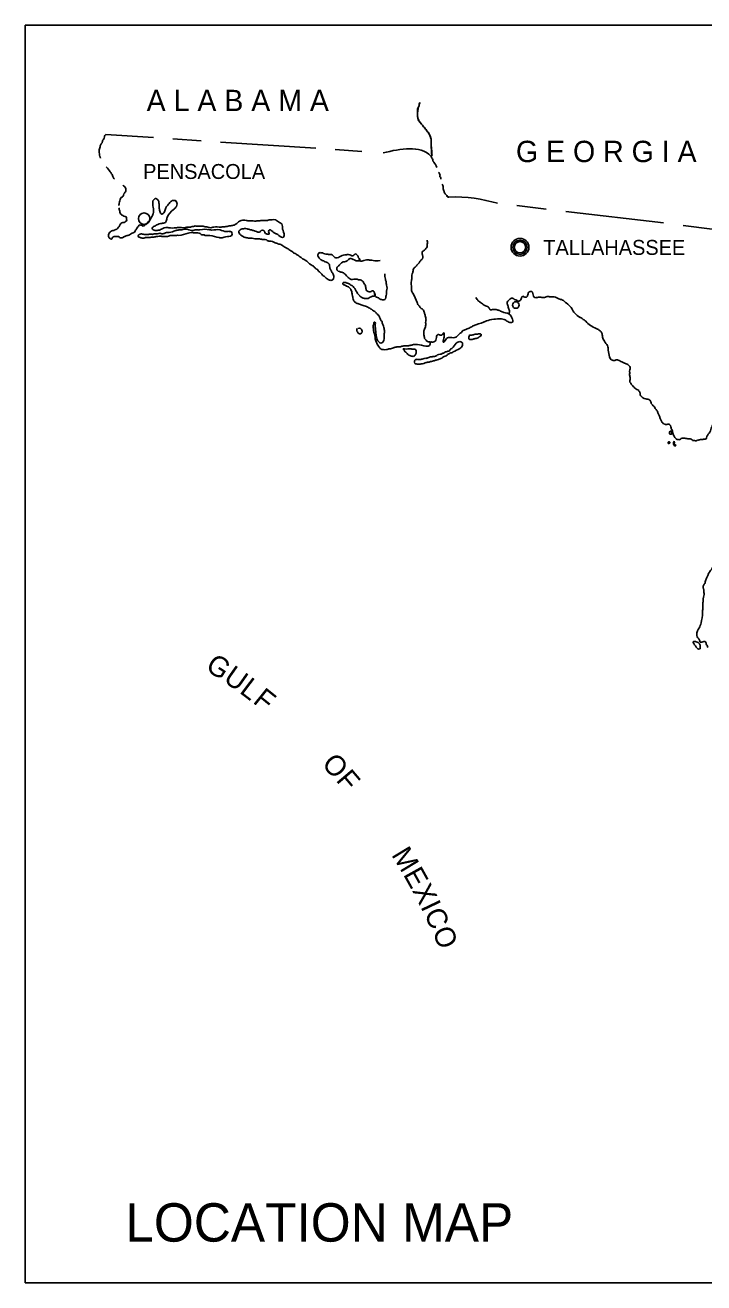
# Model space of a CAD drawing. Extents: x 565003 to 644146, y 1916234 to 1975957.
# Drawn here: x 620713 to 628733, y 1961029 to 1975886 of the extents above; entities that cross this region are included whole.
import ezdxf

# ---------------------------------------------------------------- set-up
doc = ezdxf.new("R2010")
doc.units = 0
doc.layers.add('C-TAXI-CNTR', color=7, linetype='Continuous')

msp = doc.modelspace()

# ---------------------------------------------------------------- linework, layer by layer
at = {"layer": 'C-TAXI-CNTR'}
for p, q in [((637179, 1975886), (620713, 1975886)), ((620713, 1975886), (620713, 1961029)), ((622229, 1974557), (621667, 1974595)), ((622794, 1974519), (622460, 1974542)), ((624149, 1974431), (623023, 1974505)), ((624692, 1974393), (624378, 1974415)), ((626871, 1973713), (626525, 1973754)), ((628256, 1973549), (627103, 1973685)), ((628833, 1973477), (628490, 1973520)), ((626465, 1972428), (626464, 1972430)), ((620713, 1961029), (637179, 1961029))]:
    msp.add_line(p, q, dxfattribs=at)
for centre, radius in [((622119, 1973600), 67.1), ((626561, 1973262), 105), ((626561, 1973262), 83.9), ((626561, 1973262), 67.1), ((626513, 1972580), 39)]:
    msp.add_circle(centre, radius, dxfattribs=at)
msp.add_arc((625737, 1973901), 50.8, 213.1829, 248.6294, dxfattribs=at)
for points in [[(625521, 1974345), (625517, 1974368), (625517, 1974408), (625513, 1974453), (625513, 1974506), (625505, 1974558), (625490, 1974595), (625469, 1974627), (625438, 1974668), (625397, 1974717), (625365, 1974757), (625350, 1974808), (625351, 1974869), (625356, 1974915), (625370, 1974938), (625370, 1974951), (625381, 1974974)], [(625522, 1974344), (625519, 1974353), (625519, 1974393), (625513, 1974435), (625513, 1974513), (625507, 1974551), (625493, 1974590), (625469, 1974629), (625460, 1974638), (625442, 1974665), (625421, 1974686), (625394, 1974722), (625375, 1974743), (625357, 1974780), (625351, 1974813), (625351, 1974858), (625354, 1974885), (625357, 1974896), (625360, 1974923), (625369, 1974938), (625372, 1974956), (625381, 1974974)], [(621667, 1974595), (621656, 1974584), (621650, 1974565), (621643, 1974541), (621629, 1974522), (621624, 1974503), (621618, 1974491), (621611, 1974484), (621598, 1974450), (621592, 1974425), (621588, 1974399), (621591, 1974366), (621596, 1974334), (621600, 1974323), (621604, 1974314)], [(625577, 1974206), (625542, 1974269), (625536, 1974277), (625531, 1974284), (625529, 1974296), (625520, 1974314), (625510, 1974339), (625509, 1974340), (624943, 1974378)], [(621669, 1974214), (621688, 1974195), (621701, 1974176), (621719, 1974153), (621740, 1974120), (621749, 1974098), (621768, 1974065)], [(625627, 1974067), (625625, 1974082), (625615, 1974096), (625616, 1974111), (625598, 1974149)], [(621866, 1973995), (621882, 1973983), (621898, 1973965), (621905, 1973942), (621899, 1973917), (621886, 1973903), (621863, 1973858), (621849, 1973849), (621837, 1973827), (621830, 1973797), (621823, 1973772), (621822, 1973755)], [(626295, 1973785), (625720, 1973853), (625707, 1973854), (625695, 1973873), (625676, 1973894), (625667, 1973906), (625664, 1973919), (625655, 1973939), (625654, 1973966), (625650, 1973991), (625643, 1974006)], [(621821, 1973729), (621825, 1973708), (621831, 1973690), (621834, 1973675), (621843, 1973654), (621852, 1973645), (621867, 1973636), (621894, 1973627), (621909, 1973618), (621912, 1973597), (621912, 1973574), (621900, 1973565), (621885, 1973556), (621867, 1973556), (621830, 1973517), (621818, 1973498), (621797, 1973477), (621773, 1973468), (621764, 1973462), (621749, 1973459), (621713, 1973439), (621701, 1973421), (621698, 1973400), (621698, 1973388), (621719, 1973364), (621734, 1973358), (621752, 1973385), (621782, 1973391), (621794, 1973391), (621815, 1973388), (621830, 1973379), (621854, 1973372), (621869, 1973378), (621881, 1973387), (621893, 1973390), (621908, 1973396), (621947, 1973408), (621971, 1973424), (622004, 1973442), (622019, 1973463), (622028, 1973481), (622043, 1973502), (622061, 1973522), (622082, 1973525), (622097, 1973519), (622106, 1973513), (622124, 1973519), (622133, 1973528), (622142, 1973531), (622160, 1973549), (622208, 1973619), (622226, 1973658), (622226, 1973735), (622221, 1973795), (622224, 1973811), (622236, 1973826), (622242, 1973832), (622257, 1973838), (622275, 1973829), (622295, 1973793), (622295, 1973784), (622298, 1973766), (622298, 1973729), (622304, 1973690), (622328, 1973654), (622337, 1973657), (622352, 1973669), (622373, 1973718), (622391, 1973751), (622400, 1973760), (622433, 1973801), (622451, 1973813), (622472, 1973816), (622490, 1973813), (622505, 1973789), (622508, 1973777), (622502, 1973745), (622467, 1973709), (622392, 1973615), (622380, 1973570), (622371, 1973556), (622347, 1973547), (622329, 1973544), (622269, 1973526), (622254, 1973517), (622215, 1973489), (622218, 1973474), (622236, 1973465), (622260, 1973459), (622272, 1973462), (622302, 1973465)], [(622302, 1973465), (622314, 1973472), (622332, 1973478), (622341, 1973484), (622356, 1973490), (622392, 1973496), (622410, 1973493), (622493, 1973492), (622514, 1973495), (622604, 1973495), (622643, 1973501), (622667, 1973501), (622685, 1973508), (622703, 1973508), (622724, 1973514), (622742, 1973511), (622818, 1973511), (622839, 1973505), (622860, 1973502), (622881, 1973496), (622932, 1973498), (622941, 1973501), (623028, 1973501), (623058, 1973504), (623073, 1973504), (623126, 1973514), (623147, 1973517), (623156, 1973520), (623165, 1973520), (623204, 1973535), (623213, 1973541), (623225, 1973555), (623246, 1973570), (623267, 1973579), (623324, 1973579), (623363, 1973573), (623384, 1973573), (623396, 1973574), (623423, 1973571), (623438, 1973571), (623462, 1973574), (623477, 1973574), (623516, 1973580), (623577, 1973580), (623595, 1973585), (623610, 1973585), (623631, 1973588), (623667, 1973588), (623685, 1973579), (623709, 1973561), (623745, 1973537), (623756, 1973477), (623774, 1973403), (623765, 1973382), (623741, 1973382), (623684, 1973421), (623672, 1973424), (623645, 1973442), (623639, 1973448), (623622, 1973460), (623601, 1973469), (623592, 1973460), (623592, 1973438), (623597, 1973420), (623585, 1973417), (623565, 1973420), (623547, 1973435), (623544, 1973444), (623532, 1973462), (623502, 1973459), (623490, 1973444), (623433, 1973453), (623412, 1973459), (623397, 1973465), (623355, 1973474), (623336, 1973480), (623276, 1973478), (623240, 1973454), (623262, 1973406), (623289, 1973388), (623301, 1973382), (623322, 1973376), (623361, 1973370), (623382, 1973370), (623442, 1973361), (623472, 1973361), (623516, 1973355), (623537, 1973354), (623564, 1973348), (623582, 1973339), (623591, 1973336)], [(622062, 1973414), (622061, 1973412), (622053, 1973408), (622050, 1973400), (622050, 1973390), (622053, 1973382), (622064, 1973381), (622080, 1973375), (622088, 1973373), (622095, 1973370), (622115, 1973370), (622122, 1973373), (622137, 1973376)], [(622062, 1973414), (622070, 1973415), (622077, 1973418), (622085, 1973420), (622098, 1973418)], [(622098, 1973418), (622140, 1973412), (622161, 1973412), (622179, 1973415), (622200, 1973417), (622218, 1973414), (622236, 1973420), (622260, 1973420), (622295, 1973426), (622316, 1973426), (622325, 1973420), (622337, 1973420), (622349, 1973423), (622358, 1973423), (622373, 1973433), (622394, 1973436), (622472, 1973451), (622493, 1973460), (622505, 1973463), (622514, 1973463), (622529, 1973468), (622565, 1973468), (622592, 1973474), (622628, 1973474), (622700, 1973462), (622743, 1973469), (622761, 1973466), (622779, 1973469), (622893, 1973469), (622917, 1973466), (623016, 1973468), (623090, 1973447), (623108, 1973450), (623129, 1973450), (623150, 1973444), (623159, 1973417), (623153, 1973399), (623141, 1973393), (623066, 1973382), (623042, 1973373), (623021, 1973373), (623006, 1973376), (622896, 1973400), (622863, 1973400), (622839, 1973403), (622830, 1973409), (622812, 1973408), (622794, 1973414), (622782, 1973423), (622752, 1973432), (622716, 1973432), (622692, 1973435), (622674, 1973435), (622640, 1973429), (622529, 1973403), (622502, 1973403), (622487, 1973400), (622427, 1973400), (622409, 1973393), (622385, 1973390), (622328, 1973390), (622310, 1973393), (622283, 1973390), (622271, 1973390), (622235, 1973382), (622212, 1973382), (622191, 1973379), (622173, 1973379), (622152, 1973376), (622137, 1973376)], [(623591, 1973336), (623651, 1973324), (623669, 1973315), (623690, 1973309), (623712, 1973300), (623724, 1973297), (623745, 1973288), (623760, 1973279), (623781, 1973264), (623790, 1973261), (623808, 1973249), (623820, 1973243), (623841, 1973228), (623867, 1973213), (623879, 1973204), (623885, 1973198), (623903, 1973189), (623918, 1973177), (623936, 1973168), (623960, 1973150), (623975, 1973141), (623984, 1973132), (624021, 1973111), (624093, 1973054), (624114, 1973042), (624126, 1973033), (624132, 1973024), (624144, 1973015), (624150, 1973009), (624170, 1972994), (624185, 1972976), (624197, 1972967), (624227, 1972934), (624245, 1972919), (624254, 1972913), (624269, 1972898), (624294, 1972880), (624309, 1972874), (624327, 1972871), (624345, 1972877), (624354, 1972883), (624360, 1972907), (624360, 1972922), (624353, 1972943), (624344, 1972959), (624338, 1972968), (624332, 1972983), (624320, 1973001), (624314, 1973016), (624305, 1973064), (624273, 1973085), (624249, 1973094), (624243, 1973100), (624225, 1973106), (624213, 1973115), (624204, 1973118), (624189, 1973133), (624171, 1973172), (624180, 1973190), (624192, 1973198), (624207, 1973198), (624228, 1973195), (624240, 1973189), (624270, 1973180), (624291, 1973180), (624303, 1973177), (624327, 1973177), (624342, 1973171), (624363, 1973150), (624383, 1973138), (624401, 1973138), (624428, 1973150), (624491, 1973172), (624500, 1973172), (624518, 1973175), (624536, 1973175), (624560, 1973169), (624575, 1973160), (624596, 1973169), (624614, 1973183), (624632, 1973174), (624650, 1973145), (624653, 1973136), (624659, 1973130)], [(625499, 1972130), (625496, 1972145), (625478, 1972145), (625445, 1972172), (625439, 1972178), (625427, 1972217), (625423, 1972241), (625429, 1972284), (625438, 1972305), (625447, 1972362), (625447, 1972388), (625450, 1972397), (625450, 1972418), (625445, 1972442), (625433, 1972481), (625430, 1972496), (625403, 1972536), (625385, 1972545), (625376, 1972557), (625367, 1972572), (625361, 1972578), (625351, 1972593), (625345, 1972608), (625294, 1972719), (625286, 1972731), (625280, 1972775), (625280, 1972793), (625277, 1972808), (625277, 1972865), (625283, 1972908), (625282, 1972920), (625288, 1972947), (625294, 1972962), (625303, 1973006), (625312, 1973018), (625330, 1973033), (625336, 1973042), (625351, 1973060), (625369, 1973078), (625390, 1973109), (625408, 1973127), (625411, 1973160), (625408, 1973172), (625406, 1973193), (625409, 1973213), (625424, 1973222), (625448, 1973246), (625463, 1973267), (625463, 1973288), (625466, 1973310), (625466, 1973328), (625463, 1973346)], [(624659, 1973130), (624670, 1973106), (624649, 1973100), (624626, 1973103), (624611, 1973109), (624602, 1973115), (624590, 1973118), (624572, 1973127), (624554, 1973130), (624533, 1973115), (624527, 1973109), (624512, 1973099), (624500, 1973093), (624473, 1973090), (624458, 1973084), (624443, 1973072), (624428, 1973054), (624416, 1973042), (624395, 1973010), (624401, 1972992), (624426, 1972974), (624463, 1972965), (624502, 1972935), (624523, 1972914), (624541, 1972899), (624556, 1972884), (624580, 1972881), (624617, 1972887), (624635, 1972884), (624653, 1972878), (624671, 1972877), (624695, 1972865), (624701, 1972859), (624710, 1972853), (624716, 1972839), (624731, 1972818), (624739, 1972776), (624745, 1972758), (624751, 1972746), (624766, 1972740), (624790, 1972734), (624811, 1972746), (624826, 1972749), (624841, 1972722)], [(624659, 1973130), (624673, 1973100), (624715, 1973106), (624748, 1973114), (624772, 1973114), (624781, 1973111), (624790, 1973111), (624826, 1973105), (624907, 1973105)], [(624841, 1972722), (624847, 1972692), (624865, 1972674), (624887, 1972665), (624908, 1972650), (624926, 1972644), (624944, 1972641), (624962, 1972644), (624974, 1972668), (624980, 1972694), (624983, 1972721), (624983, 1972733), (624985, 1972745), (624985, 1972815), (624979, 1972833), (624979, 1972851), (624976, 1972866), (624970, 1972884), (624962, 1972947)], [(624841, 1972722), (624847, 1972689), (624817, 1972683), (624766, 1972658), (624724, 1972658), (624709, 1972661), (624691, 1972670), (624670, 1972685), (624664, 1972691), (624635, 1972727), (624599, 1972788), (624581, 1972806), (624572, 1972812), (624554, 1972821), (624533, 1972836), (624514, 1972838), (624505, 1972844), (624496, 1972844), (624475, 1972847), (624466, 1972838), (624475, 1972820), (624485, 1972817), (624500, 1972811), (624512, 1972802), (624536, 1972793), (624557, 1972772), (624563, 1972760), (624572, 1972736), (624575, 1972724), (624578, 1972697), (624583, 1972685), (624586, 1972664), (624595, 1972638), (624604, 1972623), (624619, 1972608), (624652, 1972593), (624697, 1972578), (624719, 1972572), (624776, 1972547), (624794, 1972535), (624806, 1972529), (624830, 1972511), (624845, 1972502), (624857, 1972493), (624866, 1972481), (624886, 1972461), (624895, 1972449), (624922, 1972395), (624931, 1972383), (624934, 1972371), (624953, 1972314), (624959, 1972268), (624959, 1972250), (624956, 1972235), (624956, 1972196), (624950, 1972163), (624941, 1972143), (624917, 1972131), (624896, 1972143), (624881, 1972158), (624863, 1972220), (624857, 1972247), (624857, 1972268), (624853, 1972286), (624853, 1972301), (624850, 1972319), (624850, 1972340), (624844, 1972377), (624835, 1972374), (624832, 1972355), (624826, 1972337), (624826, 1972316), (624829, 1972292), (624829, 1972280), (624851, 1972197), (624851, 1972182), (624857, 1972158), (624881, 1972104), (624898, 1972083), (624925, 1972056), (624946, 1972053), (624982, 1972053), (625003, 1972059), (625021, 1972062), (625066, 1972074), (625078, 1972079), (625117, 1972085), (625138, 1972085), (625156, 1972091), (625198, 1972097), (625232, 1972097)], [(626465, 1972428), (626434, 1972473), (626422, 1972479), (626404, 1972485), (626371, 1972491), (626332, 1972509), (626323, 1972515), (626308, 1972518), (626290, 1972524), (626269, 1972527), (626236, 1972527), (626210, 1972523), (626198, 1972538), (626195, 1972547), (626153, 1972571), (626138, 1972577), (626096, 1972610), (626081, 1972619), (626068, 1972631), (626056, 1972644), (626038, 1972668)], [(626431, 1972478), (626437, 1972494), (626437, 1972512), (626428, 1972530), (626422, 1972556), (626410, 1972595), (626410, 1972613), (626425, 1972634), (626431, 1972640), (626452, 1972656), (626473, 1972662), (626488, 1972653), (626494, 1972647), (626527, 1972632), (626536, 1972626), (626548, 1972626), (626563, 1972632), (626575, 1972653), (626581, 1972674), (626587, 1972680), (626596, 1972683), (626608, 1972677), (626626, 1972671), (626644, 1972679), (626650, 1972691), (626656, 1972712), (626662, 1972727), (626701, 1972739), (626719, 1972685), (626737, 1972667), (626779, 1972673), (626798, 1972673), (626840, 1972667), (626861, 1972674), (626900, 1972680), (626921, 1972677), (626933, 1972677), (626996, 1972665), (627011, 1972656), (627050, 1972644), (627073, 1972632), (627085, 1972623), (627091, 1972617), (627106, 1972605), (627178, 1972530), (627185, 1972515), (627191, 1972506), (627206, 1972488), (627272, 1972434), (627284, 1972428), (627307, 1972410), (627328, 1972398), (627337, 1972389), (627461, 1972302), (627494, 1972284), (627500, 1972278), (627515, 1972269), (627524, 1972257), (627530, 1972239), (627536, 1972214), (627539, 1972190), (627550, 1972163), (627568, 1972139), (627577, 1972124), (627595, 1972100), (627604, 1972046), (627620, 1971969), (627629, 1971945), (627653, 1971927), (627671, 1971924), (627707, 1971933), (627722, 1971930), (627763, 1971909), (627772, 1971906), (627787, 1971897), (627826, 1971882), (627844, 1971870), (627859, 1971852), (627862, 1971828), (627856, 1971798), (627857, 1971783), (627857, 1971744), (627860, 1971734), (627860, 1971689), (627857, 1971680), (627869, 1971656), (627881, 1971638), (627919, 1971599), (627964, 1971569)], [(625499, 1972130), (625508, 1972145), (625520, 1972142), (625541, 1972145), (625559, 1972151), (625568, 1972164), (625583, 1972224), (625598, 1972233), (625619, 1972224), (625637, 1972224), (625655, 1972247), (625661, 1972253), (625664, 1972232), (625664, 1972200), (625657, 1972173), (625654, 1972158), (625654, 1972143), (625678, 1972161), (625693, 1972185), (625717, 1972196), (625792, 1972196), (625810, 1972205), (625846, 1972241), (625855, 1972248), (625870, 1972257), (625876, 1972266), (625909, 1972287), (625948, 1972302), (625972, 1972313), (626008, 1972334), (626131, 1972377), (626143, 1972383), (626317, 1972418), (626341, 1972418), (626372, 1972409), (626396, 1972397), (626405, 1972391), (626429, 1972379), (626450, 1972373), (626471, 1972377), (626477, 1972398), (626465, 1972428)], [(624637, 1972304), (624632, 1972296), (624631, 1972287), (624634, 1972272), (624641, 1972263), (624650, 1972248), (624658, 1972242), (624671, 1972241)], [(624646, 1972304), (624676, 1972304), (624682, 1972298), (624691, 1972283), (624695, 1972259), (624689, 1972250), (624680, 1972241), (624671, 1972241)], [(625961, 1972221), (625958, 1972200), (625958, 1972182), (625967, 1972173), (625985, 1972173), (626009, 1972176), (626024, 1972182), (626041, 1972185), (626065, 1972194), (626080, 1972203), (626101, 1972223), (626102, 1972232), (626078, 1972241)], [(625961, 1972220), (625973, 1972223), (625984, 1972223), (625991, 1972224), (626000, 1972227), (626011, 1972229), (626030, 1972235), (626039, 1972235), (626047, 1972236), (626057, 1972236), (626065, 1972239), (626078, 1972241)], [(625180, 1972064), (625195, 1972061), (625273, 1972061), (625294, 1972058), (625309, 1972059), (625330, 1972050), (625333, 1972022), (625330, 1972004), (625321, 1971989), (625307, 1971974), (625288, 1971974), (625267, 1971980), (625249, 1971989), (625231, 1972001), (625225, 1972010), (625210, 1972022)], [(625180, 1972064), (625184, 1972055), (625192, 1972047), (625201, 1972029), (625210, 1972022)], [(625232, 1972097), (625271, 1972104), (625292, 1972110), (625310, 1972113), (625349, 1972113), (625448, 1972095), (625463, 1972094), (625484, 1972097), (625496, 1972109), (625499, 1972130)], [(625355, 1971938), (625391, 1971938), (625406, 1971941), (625427, 1971950), (625448, 1971950), (625463, 1971953), (625502, 1971966), (625541, 1971972), (625580, 1971984), (625586, 1971990), (625619, 1971998), (625637, 1972004), (625649, 1972010), (625658, 1972013), (625679, 1972025), (625700, 1972031), (625733, 1972046), (625736, 1972053), (625757, 1972068), (625808, 1972128), (625850, 1972148), (625871, 1972142), (625883, 1972118), (625880, 1972106), (625870, 1972083), (625849, 1972065), (625771, 1972026), (625753, 1972016), (625732, 1972010), (625726, 1972004), (625714, 1972001), (625699, 1971989), (625675, 1971974), (625657, 1971968), (625636, 1971954), (625597, 1971936), (625571, 1971930), (625556, 1971924), (625538, 1971921), (625514, 1971914), (625478, 1971905), (625460, 1971902), (625424, 1971890), (625364, 1971882)], [(625355, 1971938), (625336, 1971938), (625327, 1971935), (625319, 1971930), (625316, 1971921), (625315, 1971909), (625312, 1971900), (625319, 1971894), (625322, 1971887), (625334, 1971885), (625342, 1971882), (625364, 1971882)], [(627964, 1971569), (627970, 1971560), (627976, 1971554), (627979, 1971539), (627991, 1971504), (627997, 1971498), (628019, 1971480), (628034, 1971474), (628058, 1971468), (628073, 1971467), (628094, 1971455), (628103, 1971446), (628109, 1971426), (628127, 1971399), (628136, 1971390), (628168, 1971345), (628189, 1971312), (628192, 1971300), (628198, 1971291), (628241, 1971193), (628247, 1971187), (628271, 1971172), (628286, 1971169), (628328, 1971168), (628343, 1971142), (628349, 1971121), (628357, 1971109), (628363, 1971079), (628381, 1971031), (628390, 1971016), (628405, 1970998), (628420, 1970992), (628438, 1970989), (628477, 1971007), (628499, 1971007), (628544, 1971001), (628595, 1970986), (628601, 1970980), (628613, 1970979), (628652, 1970979), (628658, 1970985), (628670, 1970985), (628694, 1970991), (628709, 1970991), (628730, 1970997)], [(628730, 1970997), (628760, 1971000), (628769, 1971028), (628775, 1971040), (628811, 1971094), (628820, 1971126), (628826, 1971138), (628847, 1971192), (628847, 1971201), (628853, 1971226), (628855, 1971238), (628855, 1971274), (628858, 1971295), (628858, 1971316), (628855, 1971331), (628853, 1971453), (628856, 1971471), (628856, 1971486), (628862, 1971521), (628868, 1971530), (628874, 1971551)], [(628328, 1971058), (628328, 1971079), (628346, 1971091), (628352, 1971073)], [(628328, 1971058), (628336, 1971054), (628345, 1971054), (628352, 1971055), (628355, 1971063), (628352, 1971073)], [(628333, 1970958), (628330, 1970950), (628322, 1970946), (628315, 1970944), (628310, 1970952), (628312, 1970961)], [(628312, 1970961), (628321, 1970964), (628333, 1970958)], [(628381, 1970970), (628375, 1970958), (628375, 1970940), (628384, 1970922), (628402, 1970916)], [(628381, 1970970), (628384, 1970962), (628385, 1970955), (628382, 1970940), (628390, 1970937), (628402, 1970916)], [(628838, 1970746), (628859, 1970701), (628847, 1970689), (628844, 1970670), (628852, 1970649), (628867, 1970625), (628885, 1970610), (628906, 1970598), (628912, 1970592), (628924, 1970574), (628927, 1970550), (628927, 1970535), (628933, 1970514), (628943, 1970502), (628964, 1970484), (628979, 1970478), (629006, 1970472), (629018, 1970463), (629021, 1970437), (629015, 1970425), (629009, 1970416), (628997, 1970404), (628958, 1970392), (628943, 1970380), (628931, 1970349), (628931, 1970337), (628928, 1970319), (628951, 1970241), (628957, 1970220), (628963, 1970206), (628969, 1970185), (628978, 1970164), (628982, 1970110), (628982, 1970086), (628979, 1970064), (628979, 1970043), (628976, 1970034), (628976, 1970019), (628973, 1970004), (628973, 1969992), (628969, 1969855), (628966, 1969834), (628957, 1969819), (628924, 1969779), (628921, 1969764), (628918, 1969755), (628916, 1969681), (628898, 1969642), (628895, 1969624), (628877, 1969584), (628856, 1969521), (628847, 1969503), (628841, 1969494), (628837, 1969480), (628804, 1969432), (628798, 1969420), (628786, 1969402), (628774, 1969368), (628765, 1969353), (628750, 1969311), (628744, 1969290), (628732, 1969273), (628726, 1969261), (628726, 1969237), (628730, 1969225), (628733, 1969213), (628733, 1969198), (628736, 1969174), (628736, 1969159), (628724, 1969095), (628724, 1969074), (628721, 1969056), (628723, 1969015), (628720, 1968997), (628720, 1968982), (628717, 1968958), (628717, 1968946), (628700, 1968825), (628679, 1968766), (628658, 1968730), (628652, 1968709), (628652, 1968676), (628664, 1968648), (628670, 1968642), (628684, 1968612), (628693, 1968597), (628732, 1968606), (628753, 1968601), (628765, 1968567), (628771, 1968558), (628780, 1968534)], [(628643, 1968601), (628634, 1968606), (628625, 1968606), (628613, 1968604), (628606, 1968601), (628607, 1968594), (628615, 1968582)], [(628642, 1968603), (628682, 1968579), (628691, 1968540), (628688, 1968520), (628661, 1968520), (628655, 1968526), (628615, 1968582)]]:
    msp.add_spline(points, degree=3, dxfattribs=at)

# ---------------------------------------------------------------- texts
for s, height, rotation, p in [('A L A B A M A', 252.03, 0, (622149, 1974870)), ('G E O R G I A', 252.03, 0, (626513, 1974268)), ('PENSACOLA', 176.4, 0, (622107, 1974069)), ('TALLAHASSEE', 176.42, 0, (626836, 1973172)), ('G', 240, 326.9162, (622832, 1968277)), ('U', 240, 324.8526, (623044, 1968140)), ('L', 240, 322.9366, (623235, 1968005)), ('F', 240, 321.3158, (623394, 1967887)), ('O', 240, 312.3292, (624208, 1967151)), ('F', 240, 310.2656, (624378, 1966964)), ('M', 240, 301.279, (625036, 1966086)), ('E', 240, 299.0692, (625176, 1965855)), ('X', 240, 297.2994, (625282, 1965666)), ('I', 240, 295.5296, (625382, 1965474)), ('C', 240, 294.793, (625422, 1965393)), ('O', 240, 292.877, (625520, 1965181)), ('LOCATION MAP', 453.65, 0, (621897, 1961516))]:
    msp.add_text(s, height=height, rotation=rotation, dxfattribs=at).set_placement(p)

doc.saveas('drawing.dxf')
